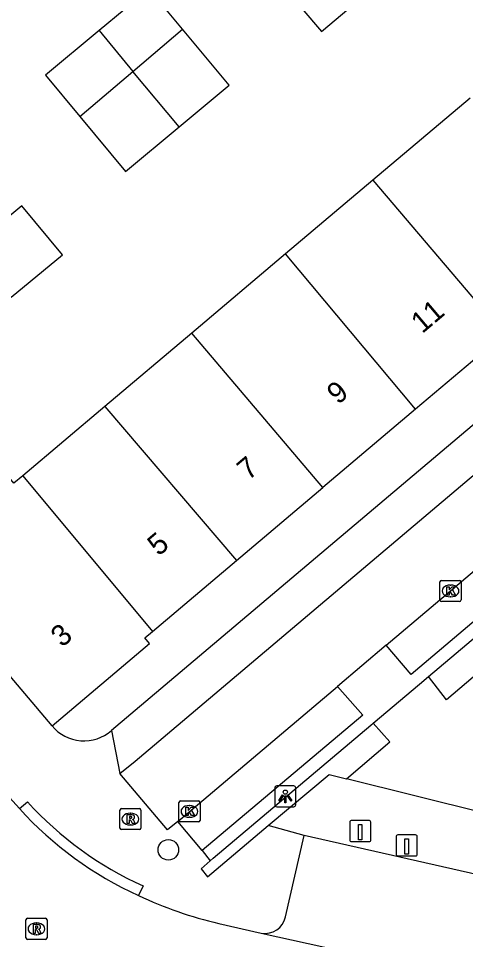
# Model space of a CAD drawing. Extents: x 162172 to 163187, y 382874 to 383684.
# Drawn here: x 162298.96 to 162320.19, y 383135.64 to 383179.43 of the extents above; entities that cross this region are included whole.
import ezdxf

# ---------------------------------------------------------------- set-up
doc = ezdxf.new("R2010")
doc.units = 0
for name, color, linetype in [('IMGEO_Boom', 7, 'Continuous'), ('IMGEO_Groenvoorziening', 7, 'Continuous'), ('IMGEO_Haag', 7, 'Continuous'), ('IMGEO_Kolk', 7, 'Continuous'), ('IMGEO_Laadpaal', 7, 'Continuous'), ('IMGEO_Lichtpunt', 7, 'Continuous'), ('IMGEO_Pand', 7, 'Continuous'), ('IMGEO_Pand_nummerreeks', 7, 'Continuous'), ('IMGEO_Parkeervlak_open', 7, 'Continuous'), ('IMGEO_Rijbaan_lokaal_open', 7, 'Continuous'), ('IMGEO_Rioolput', 7, 'Continuous'), ('IMGEO_Voetpad_open', 7, 'Continuous')]:
    doc.layers.add(name, color=color, linetype=linetype)

msp = doc.modelspace()

# ---------------------------------------------------------------- linework, layer by layer
at = {"layer": 'IMGEO_Boom'}
msp.add_circle((162306.077, 383139.907), 0.489, dxfattribs=at)
at = {"layer": 'IMGEO_Groenvoorziening'}
msp.add_lwpolyline([(162321.096, 383141.652), (162314.53, 383143.278)], dxfattribs=at)
at = {"layer": 'IMGEO_Haag'}
for points in [[(162335.202, 383162.307), (162336.048, 383161.296), (162319.29, 383147.041), (162318.422, 383148.141)], [(162314.53, 383143.278), (162316.588, 383145.037), (162315.804, 383145.93)], [(162310.809, 383141.063), (162313.707, 383143.482), (162314.53, 383143.278)]]:
    msp.add_lwpolyline(points, dxfattribs=at)
at = {"layer": 'IMGEO_Kolk'}
for p, q in [((162318.974, 383151.787), (162318.974, 383152.639)), ((162319.049, 383152.713), (162319.901, 383152.713)), ((162319.462, 383152.493), (162319.487, 383152.493)), ((162319.975, 383152.639), (162319.975, 383151.787)), ((162319.485, 383151.933), (162319.46, 383151.933)), ((162319.901, 383151.713), (162319.049, 383151.713)), ((162306.655, 383142.233), (162307.507, 383142.233)), ((162306.58, 383141.307), (162306.58, 383142.159)), ((162307.068, 383142.013), (162307.093, 383142.013)), ((162307.581, 383142.159), (162307.581, 383141.307)), ((162307.091, 383141.453), (162307.066, 383141.453)), ((162307.507, 383141.233), (162306.655, 383141.233))]:
    msp.add_line(p, q, dxfattribs=at)
for points in [[(162318.974, 383151.787), (162318.974, 383152.639)], [(162319.049, 383152.713), (162319.901, 383152.713)], [(162319.295, 383152.413), (162319.418, 383152.413), (162319.418, 383152.262), (162319.548, 383152.413), (162319.712, 383152.413), (162319.566, 383152.262), (162319.719, 383152.013), (162319.567, 383152.013), (162319.482, 383152.177), (162319.418, 383152.11), (162319.418, 383152.013), (162319.295, 383152.013), (162319.295, 383152.413)], [(162319.975, 383152.639), (162319.975, 383151.787)], [(162319.901, 383151.713), (162319.049, 383151.713)], [(162306.655, 383142.233), (162307.507, 383142.233)], [(162306.58, 383141.307), (162306.58, 383142.159)], [(162306.901, 383141.933), (162307.024, 383141.933), (162307.024, 383141.782), (162307.154, 383141.933), (162307.318, 383141.933), (162307.172, 383141.782), (162307.325, 383141.533), (162307.173, 383141.533), (162307.088, 383141.697), (162307.024, 383141.63), (162307.024, 383141.533), (162306.901, 383141.533), (162306.901, 383141.933)], [(162307.581, 383142.159), (162307.581, 383141.307)], [(162307.507, 383141.233), (162306.655, 383141.233)]]:
    msp.add_lwpolyline(points, dxfattribs=at)
for centre, start, end in [((162319.051, 383152.637), 91.552, 178.448), ((162319.051, 383152.637), 91.552, 178.448), ((162319.899, 383152.637), 1.552, 88.448), ((162319.899, 383152.637), 1.552, 88.448), ((162319.051, 383151.789), 181.552, 268.448), ((162319.051, 383151.789), 181.552, 268.448), ((162319.899, 383151.789), 271.552, 358.448), ((162319.899, 383151.789), 271.552, 358.448), ((162306.657, 383142.157), 91.552, 178.448), ((162306.657, 383142.157), 91.552, 178.448), ((162307.505, 383142.157), 1.552, 88.448), ((162307.505, 383142.157), 1.552, 88.448), ((162306.657, 383141.309), 181.552, 268.448), ((162306.657, 383141.309), 181.552, 268.448), ((162307.505, 383141.309), 271.552, 358.448), ((162307.505, 383141.309), 271.552, 358.448)]:
    msp.add_arc(centre, 0.0765, start, end, dxfattribs=at)
for centre, major_axis, ratio, start_param, end_param in [((162319.461, 383152.213), (-0.387, 0.002), 0.722429, 4.712389, 7.853982), ((162319.486, 383152.213), (-0.39, 0.002), 0.717154, 1.570796, 4.712389), ((162307.067, 383141.733), (-0.387, 0.002), 0.722429, 4.712389, 7.853982), ((162307.092, 383141.733), (-0.39, 0.002), 0.717154, 1.570796, 4.712389)]:
    msp.add_ellipse(centre, major_axis=major_axis, ratio=ratio, start_param=start_param, end_param=end_param, dxfattribs=at)
at = {"layer": 'IMGEO_Laadpaal'}
for p, q in [((162314.689, 383141.216), (162314.689, 383140.375)), ((162314.689, 383141.216), (162314.689, 383140.375)), ((162315.605, 383141.3), (162314.764, 383141.3)), ((162315.605, 383141.3), (162314.764, 383141.3)), ((162315.689, 383140.384), (162315.689, 383141.225)), ((162315.689, 383140.384), (162315.689, 383141.225)), ((162316.898, 383140.532), (162316.898, 383139.691)), ((162316.898, 383140.532), (162316.898, 383139.691)), ((162317.814, 383140.616), (162316.973, 383140.616)), ((162317.814, 383140.616), (162316.973, 383140.616)), ((162317.898, 383139.7), (162317.898, 383140.541)), ((162317.898, 383139.7), (162317.898, 383140.541)), ((162314.773, 383140.3), (162315.614, 383140.3)), ((162314.773, 383140.3), (162315.614, 383140.3)), ((162316.982, 383139.616), (162317.823, 383139.616)), ((162316.982, 383139.616), (162317.823, 383139.616))]:
    msp.add_line(p, q, dxfattribs=at)
for points in [[(162315.104, 383141.113), (162315.264, 383141.113), (162315.264, 383140.38), (162315.104, 383140.38), (162315.104, 383141.113)], [(162317.313, 383140.429), (162317.473, 383140.429), (162317.473, 383139.696), (162317.313, 383139.696), (162317.313, 383140.429)]]:
    msp.add_lwpolyline(points, dxfattribs=at)
for centre, start, end in [((162314.767, 383141.222), 92.4484, 184.2845), ((162314.767, 383141.222), 92.4484, 184.2845), ((162315.611, 383141.222), 2.4484, 94.2845), ((162315.611, 383141.222), 2.4484, 94.2845), ((162316.976, 383140.538), 92.4484, 184.2845), ((162316.976, 383140.538), 92.4484, 184.2845), ((162317.82, 383140.538), 2.4484, 94.2845), ((162317.82, 383140.538), 2.4484, 94.2845), ((162314.767, 383140.378), 182.4484, 274.2845), ((162314.767, 383140.378), 182.4484, 274.2845), ((162315.611, 383140.378), 272.4484, 4.2845), ((162315.611, 383140.378), 272.4484, 4.2845), ((162316.976, 383139.694), 182.4484, 274.2845), ((162316.976, 383139.694), 182.4484, 274.2845), ((162317.82, 383139.694), 272.4484, 4.2845), ((162317.82, 383139.694), 272.4484, 4.2845)]:
    msp.add_arc(centre, 0.0779, start, end, dxfattribs=at)
at = {"layer": 'IMGEO_Lichtpunt'}
for p, q in [((162311.131, 383142.854), (162311.131, 383142.047)), ((162311.131, 383142.854), (162311.131, 383142.047)), ((162312.033, 383142.949), (162311.225, 383142.949)), ((162312.033, 383142.949), (162311.225, 383142.949)), ((162312.127, 383142.047), (162312.127, 383142.854)), ((162312.127, 383142.047), (162312.127, 383142.854)), ((162311.225, 383141.953), (162312.033, 383141.953)), ((162311.225, 383141.953), (162312.033, 383141.953))]:
    msp.add_line(p, q, dxfattribs=at)
for points in [[(162311.505, 383142.518), (162311.544, 383142.49), (162311.356, 383142.228), (162311.318, 383142.255), (162311.505, 383142.518)], [(162311.607, 383142.47), (162311.654, 383142.47), (162311.654, 383142.148), (162311.607, 383142.148), (162311.607, 383142.47)], [(162311.717, 383142.49), (162311.755, 383142.517), (162311.942, 383142.255), (162311.903, 383142.227), (162311.717, 383142.49)]]:
    msp.add_lwpolyline(points, dxfattribs=at)
msp.add_circle((162311.63, 383142.652), 0.0994, dxfattribs=at)
for centre, start, end in [((162311.225, 383142.854), 90, 180), ((162311.225, 383142.854), 90, 180), ((162312.033, 383142.854), 0, 90), ((162312.033, 383142.854), 0, 90), ((162311.225, 383142.047), 180, 270), ((162311.225, 383142.047), 180, 270), ((162312.033, 383142.047), 270, 0), ((162312.033, 383142.047), 270, 360)]:
    msp.add_arc(centre, 0.0946, start, end, dxfattribs=at)
at = {"layer": 'IMGEO_Pand'}
for points in [[(162314.005, 383183.33), (162311.387, 383181.118), (162313.343, 383178.804), (162315.943, 383181.001)], [(162306.746, 383178.921), (162305.161, 383180.826), (162302.786, 383178.85)], [(162302.786, 383178.85), (162300.239, 383176.73), (162301.878, 383174.761)], [(162302.786, 383178.85), (162304.393, 383176.91)], [(162304.393, 383176.91), (162306.746, 383178.921)], [(162306.593, 383174.276), (162308.967, 383176.252), (162306.746, 383178.921)], [(162301.878, 383174.761), (162304.393, 383176.91)], [(162306.593, 383174.276), (162304.393, 383176.91)], [(162320.403, 383175.643), (162315.788, 383171.741)], [(162301.878, 383174.761), (162304.045, 383172.156), (162306.593, 383174.276)], [(162315.788, 383171.741), (162311.64, 383168.234)], [(162315.788, 383171.741), (162322.016, 383164.402)], [(162298.619, 383166.183), (162301.048, 383168.19), (162299.124, 383170.518), (162296.657, 383168.479)], [(162311.64, 383168.234), (162307.191, 383164.472)], [(162317.811, 383160.846), (162311.64, 383168.234)], [(162307.191, 383164.472), (162303.063, 383160.983)], [(162313.413, 383157.129), (162307.191, 383164.472)], [(162322.016, 383164.402), (162317.811, 383160.846)], [(162303.063, 383160.983), (162299.171, 383157.692)], [(162303.063, 383160.983), (162309.316, 383153.666)], [(162317.811, 383160.846), (162313.413, 383157.129)], [(162299.171, 383157.692), (162298.744, 383157.331), (162298.518, 383157.598), (162293.888, 383153.688)], [(162299.171, 383157.692), (162305.323, 383150.29)], [(162309.316, 383153.666), (162313.413, 383157.129)], [(162300.554, 383145.796), (162293.888, 383153.688)], [(162305.323, 383150.29), (162309.316, 383153.666)], [(162300.554, 383145.796), (162305.184, 383149.712), (162304.962, 383149.985), (162305.323, 383150.29)]]:
    msp.add_lwpolyline(points, dxfattribs=at)
at = {"layer": 'IMGEO_Parkeervlak_open'}
msp.add_lwpolyline([(162336.083, 383135.244), (162312.528, 383140.586)], dxfattribs=at)
at = {"layer": 'IMGEO_Rijbaan_lokaal_open'}
for points in [[(162303.781, 383143.539), (162304.504, 383144.126), (162342.05, 383175.889)], [(162316.419, 383149.634), (162319.473, 383152.215), (162328.815, 383160.146), (162333.613, 383164.164)], [(162316.419, 383149.634), (162314.114, 383147.678)], [(162306.524, 383141.258), (162307.054, 383141.705), (162314.114, 383147.678)], [(162306.524, 383141.258), (162306.044, 383140.853), (162303.781, 383143.539)], [(162298.527, 383142.396), (162299.002, 383141.868)], [(162308.476, 383136.406), (162310.489, 383135.954)], [(162310.489, 383135.954), (162315.736, 383134.794), (162332.866, 383130.889), (162335.861, 383130.194)]]:
    msp.add_lwpolyline(points, dxfattribs=at)
for centre, radius, start, end in [((162311.819, 383153.496), 17.306, 222.2169, 245.5865), ((162311.461, 383152.145), 22.213, 217.546, 248.5501), ((162312.712, 383154.638), 18.717, 244.5405, 256.9196)]:
    msp.add_arc(centre, radius, start, end, dxfattribs=at)
at = {"layer": 'IMGEO_Rioolput'}
for p, q in [((162303.776, 383140.942), (162303.776, 383141.794)), ((162303.851, 383141.868), (162304.703, 383141.868)), ((162304.777, 383141.794), (162304.777, 383140.942)), ((162304.264, 383141.648), (162304.289, 383141.648)), ((162304.287, 383141.088), (162304.262, 383141.088)), ((162304.703, 383140.868), (162303.851, 383140.868)), ((162299.315, 383135.727), (162299.315, 383136.579)), ((162299.39, 383136.653), (162300.242, 383136.653)), ((162300.316, 383136.579), (162300.316, 383135.727)), ((162299.803, 383136.433), (162299.828, 383136.433)), ((162299.826, 383135.873), (162299.801, 383135.873)), ((162300.242, 383135.653), (162299.39, 383135.653))]:
    msp.add_line(p, q, dxfattribs=at)
for points in [[(162303.776, 383140.942), (162303.776, 383141.794)], [(162303.851, 383141.868), (162304.703, 383141.868)], [(162304.777, 383141.794), (162304.777, 383140.942)], [(162304.365, 383141.566), (162304.113, 383141.568), (162304.113, 383141.168)], [(162304.291, 383141.487), (162304.237, 383141.487), (162304.237, 383141.406)], [(162304.237, 383141.406), (162304.289, 383141.406)], [(162304.113, 383141.168), (162304.237, 383141.168), (162304.237, 383141.33), (162304.248, 383141.33)], [(162304.295, 383141.301), (162304.366, 383141.168), (162304.506, 383141.168), (162304.441, 383141.294)], [(162304.703, 383140.868), (162303.851, 383140.868)], [(162299.315, 383135.727), (162299.315, 383136.579)], [(162299.39, 383136.653), (162300.242, 383136.653)], [(162300.316, 383136.579), (162300.316, 383135.727)], [(162299.904, 383136.351), (162299.652, 383136.353), (162299.652, 383135.953)], [(162299.652, 383135.953), (162299.776, 383135.953), (162299.776, 383136.115), (162299.787, 383136.115)], [(162299.83, 383136.272), (162299.776, 383136.272), (162299.776, 383136.191)], [(162299.776, 383136.191), (162299.828, 383136.191)], [(162299.834, 383136.086), (162299.905, 383135.953), (162300.045, 383135.953), (162299.98, 383136.079)], [(162300.242, 383135.653), (162299.39, 383135.653)]]:
    msp.add_lwpolyline(points, dxfattribs=at)
for centre, radius, start, end in [((162303.853, 383141.792), 0.0765, 91.552, 178.448), ((162303.853, 383141.792), 0.0765, 91.552, 178.448), ((162304.701, 383141.792), 0.0765, 1.552, 88.448), ((162304.701, 383141.792), 0.0765, 1.552, 88.448), ((162304.273, 383141.595), 0.19, 274.7715, 282.9687), ((162304.297, 383141.391), 0.0964, 77.0061, 93.1865), ((162304.311, 383141.448), 0.0378, 276.6634, 79.6772), ((162304.364, 383141.456), 0.109, 350.3612, 89.416), ((162304.362, 383141.456), 0.112, 277.5842, 350.9817), ((162303.853, 383140.944), 0.0765, 181.552, 268.448), ((162303.853, 383140.944), 0.0765, 181.552, 268.448), ((162304.247, 383141.277), 0.0533, 26.0293, 88.6989), ((162304.346, 383141.241), 0.108, 29.5134, 73.7905), ((162304.701, 383140.944), 0.0765, 271.552, 358.448), ((162304.701, 383140.944), 0.0765, 271.552, 358.448), ((162299.392, 383136.577), 0.0765, 91.552, 178.448), ((162299.392, 383136.577), 0.0765, 91.552, 178.448), ((162300.24, 383136.577), 0.0765, 1.552, 88.448), ((162300.24, 383136.577), 0.0765, 1.552, 88.448), ((162299.786, 383136.062), 0.0533, 26.0293, 88.6989), ((162299.812, 383136.38), 0.19, 274.7715, 282.9687), ((162299.836, 383136.176), 0.0964, 77.0061, 93.1865), ((162299.85, 383136.233), 0.0378, 276.6634, 79.6772), ((162299.903, 383136.241), 0.109, 350.3612, 89.416), ((162299.901, 383136.241), 0.112, 277.5842, 350.9817), ((162299.885, 383136.026), 0.108, 29.5134, 73.7905), ((162299.392, 383135.729), 0.0765, 181.552, 268.448), ((162299.392, 383135.729), 0.0765, 181.552, 268.448), ((162300.24, 383135.729), 0.0765, 271.552, 358.448), ((162300.24, 383135.729), 0.0765, 271.552, 358.448)]:
    msp.add_arc(centre, radius, start, end, dxfattribs=at)
for centre, major_axis, ratio, start_param, end_param in [((162304.263, 383141.368), (-0.387, 0.002), 0.722429, 4.712389, 7.853982), ((162304.288, 383141.368), (-0.39, 0.002), 0.717154, 1.570796, 4.712389), ((162299.802, 383136.153), (-0.387, 0.002), 0.722429, 4.712389, 7.853982), ((162299.827, 383136.153), (-0.39, 0.002), 0.717154, 1.570796, 4.712389)]:
    msp.add_ellipse(centre, major_axis=major_axis, ratio=ratio, start_param=start_param, end_param=end_param, dxfattribs=at)
at = {"layer": 'IMGEO_Voetpad_open'}
for points in [[(162339.665, 383176.277), (162303.372, 383145.574)], [(162333.613, 383164.164), (162334.784, 383162.792), (162317.605, 383148.249), (162316.419, 383149.634)], [(162318.422, 383148.141), (162335.202, 383162.307)], [(162315.804, 383145.93), (162318.003, 383147.787), (162318.422, 383148.141)], [(162314.114, 383147.678), (162315.305, 383146.31), (162307.689, 383139.879)], [(162308.056, 383139.384), (162308.203, 383139.513), (162315.689, 383145.833), (162315.804, 383145.93)], [(162303.372, 383145.574), (162303.781, 383143.539)], [(162299.002, 383141.868), (162299.387, 383142.187)], [(162307.689, 383139.879), (162306.524, 383141.258)], [(162308.056, 383139.384), (162307.63, 383139.008), (162307.936, 383138.621), (162310.809, 383141.063)], [(162312.528, 383140.586), (162310.809, 383141.063)], [(162311.64, 383136.721), (162312.528, 383140.586)], [(162307.689, 383139.879), (162308.056, 383139.384)], [(162304.883, 383138.189), (162304.666, 383137.738)]]:
    msp.add_lwpolyline(points, dxfattribs=at)
for centre, radius, start, end in [((162302.073, 383147.076), 1.986, 220.1253, 310.8659), ((162311.814, 383153.494), 16.801, 222.2974, 245.6355), ((162310.672, 383136.926), 0.989, 259.3211, 348.0361)]:
    msp.add_arc(centre, radius, start, end, dxfattribs=at)

# ---------------------------------------------------------------- texts
at = {"layer": 'IMGEO_Pand_nummerreeks'}
for s, rotation, p in [('11', 40.2091, (162318.132, 383164.418)), ('9', 40.2091, (162314.136, 383161.04)), ('7', 40.2091, (162309.876, 383157.438)), ('5', 40.2091, (162305.616, 383153.837)), ('3', 40.2242, (162301.031, 383149.5))]:
    msp.add_text(s, height=1, rotation=rotation, dxfattribs=at).set_placement(p)

doc.saveas('drawing.dxf')
